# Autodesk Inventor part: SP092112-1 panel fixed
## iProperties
Created: 2012-09
Part Number: SP092112-1 panel fixed
Material: Polycarbonate, Clear
Document SubType Name: Modeling
Designer: Administrator
Mass: 16536.2 g
Surface Area: 49686.2 cm^2
Volume: 13780.1 cm^3
Density: 1.2 g/cm^3
Author: Administrator
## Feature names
1. Extrusion1
